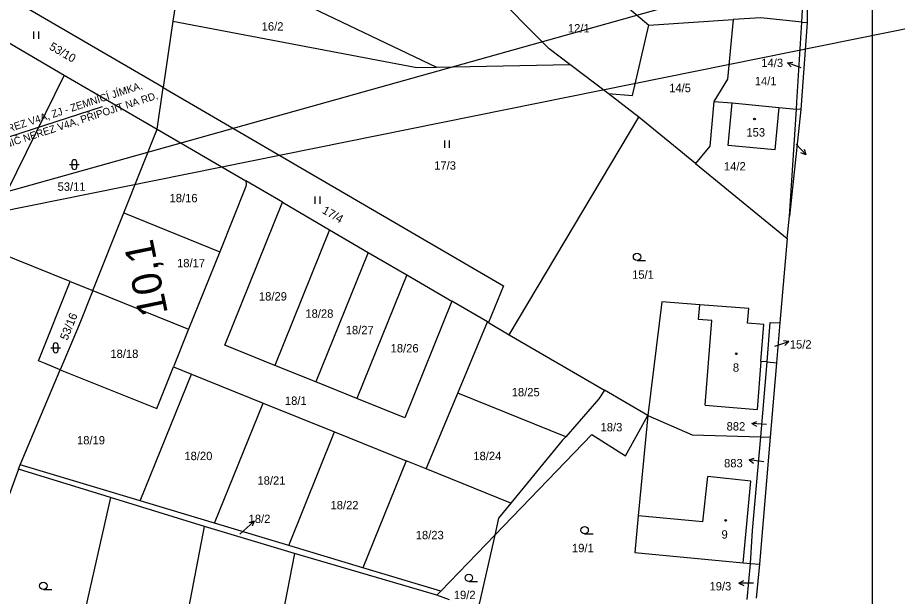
# Model space of a CAD drawing. Extents: x -553916 to -552953, y -1067470 to -1066637.
# Drawn here: x -553473.7 to -553294.9, y -1067063.1 to -1066945.3 of the extents above; entities that cross this region are included whole.
import ezdxf

# ---------------------------------------------------------------- set-up
doc = ezdxf.new("R2010")
doc.units = 0
for name, color, linetype in [('Hranice parcel', 7, 'Continuous'), ('Návěst místo trati', 7, 'Continuous'), ('Parcelní čísla', 7, 'Continuous'), ('Pop  PČ popisy', 7, 'Continuous'), ('trasa_NN_popisky', 7, 'Continuous'), ('Vnitřní kresba', 7, 'Continuous'), ('Vrstva 1', 7, 'Continuous'), ('Vrstva 28', 7, 'Continuous'), ('Značky budov', 7, 'Continuous'), ('Značky kultur', 7, 'Continuous')]:
    doc.layers.add(name, color=color, linetype=linetype)

msp = doc.modelspace()

# ---------------------------------------------------------------- linework, layer by layer
at = {"layer": 'Hranice parcel'}
for p, q in [((-553439.39, -1066931.05), (-553388.55, -1066955.44)), ((-553440.62, -1066935.71), (-553442.13, -1066946.08)), ((-553440.62, -1066935.71), (-553442.13, -1066946.08)), ((-553313.3, -1066937.87), (-553313.24, -1066946.37)), ((-553349.32, -1066943.54), (-553345.38, -1066946.85)), ((-553442.13, -1066946.08), (-553444.09, -1066959.55)), ((-553442.13, -1066946.08), (-553444.09, -1066959.55)), ((-553345.38, -1066946.85), (-553328.25, -1066945.75)), ((-553328.25, -1066945.75), (-553329.39, -1066957.87)), ((-553313.24, -1066946.37), (-553314.48, -1066964.04)), ((-553314.33, -1066946.26), (-553313.24, -1066946.37)), ((-553388.55, -1066955.44), (-553361.44, -1066954.89)), ((-553353.69, -1066960.78), (-553361.44, -1066954.89)), ((-553464.25, -1066957.05), (-553481.25, -1066991.64)), ((-553464.25, -1066957.05), (-553445.33, -1066968.05)), ((-553329.39, -1066957.87), (-553332.16, -1066962.42)), ((-553445.33, -1066968.05), (-553444.09, -1066959.55)), ((-553445.33, -1066968.05), (-553444.09, -1066959.55)), ((-553347.4, -1066965.57), (-553353.69, -1066960.78)), ((-553332.16, -1066962.42), (-553328.45, -1066962.7)), ((-553328.45, -1066962.7), (-553318.99, -1066963.61)), ((-553318.99, -1066963.61), (-553315.39, -1066963.95)), ((-553316.83, -1066985.76), (-553315.39, -1066963.95)), ((-553314.48, -1066964.04), (-553316.83, -1066985.76)), ((-553314.48, -1066964.04), (-553315.39, -1066963.95)), ((-553373.76, -1067009.84), (-553347.4, -1066965.57)), ((-553335.89, -1066975.02), (-553347.4, -1066965.57)), ((-553452.1, -1066985.07), (-553445.33, -1066968.05)), ((-553452.1, -1066985.07), (-553445.33, -1066968.05)), ((-553445.33, -1066968.05), (-553427.32, -1066978.56)), ((-553335.89, -1066975.02), (-553317.32, -1066990.26)), ((-553419.87, -1066982.91), (-553427.32, -1066978.56)), ((-553419.87, -1066982.91), (-553410.27, -1066988.51)), ((-553458.39, -1067000.88), (-553452.1, -1066985.07)), ((-553458.39, -1067000.88), (-553452.1, -1066985.07)), ((-553452.1, -1066985.07), (-553432.61, -1066992.95)), ((-553317.32, -1066990.26), (-553316.83, -1066985.76)), ((-553410.27, -1066988.51), (-553421.4, -1067016.07)), ((-553410.27, -1066988.51), (-553402.41, -1066993.09)), ((-553317.32, -1066990.26), (-553318.77, -1067007.4)), ((-553463.03, -1066999), (-553481.25, -1066991.64)), ((-553432.61, -1066992.95), (-553438.95, -1067008.73)), ((-553402.41, -1066993.09), (-553413.06, -1067019.44)), ((-553402.41, -1066993.09), (-553394.55, -1066997.68)), ((-553394.55, -1066997.68), (-553404.71, -1067022.81)), ((-553394.55, -1066997.68), (-553385.42, -1067003.02)), ((-553463.03, -1066999), (-553458.39, -1067000.88)), ((-553458.39, -1067000.88), (-553438.95, -1067008.73)), ((-553378.18, -1067007.25), (-553385.42, -1067003.02)), ((-553384.24, -1067021.73), (-553378.18, -1067007.25)), ((-553378.18, -1067007.25), (-553377.98, -1067007.37)), ((-553438.95, -1067008.73), (-553442.02, -1067016.38)), ((-553377.98, -1067007.37), (-553373.76, -1067009.84)), ((-553318.77, -1067007.4), (-553319.46, -1067015.54)), ((-553373.76, -1067009.84), (-553354.43, -1067021.12)), ((-553413.06, -1067019.44), (-553421.4, -1067016.07)), ((-553322.61, -1067030.64), (-553321.33, -1067015.39)), ((-553321.33, -1067015.39), (-553319.46, -1067015.54)), ((-553319.46, -1067015.54), (-553320.75, -1067030.7)), ((-553473.16, -1067036.3), (-553465, -1067016.95)), ((-553473.16, -1067036.3), (-553465, -1067016.95)), ((-553448.77, -1067043.63), (-553438.35, -1067017.86)), ((-553442.02, -1067016.38), (-553438.35, -1067017.86)), ((-553438.35, -1067017.86), (-553423.8, -1067023.74)), ((-553404.71, -1067022.81), (-553413.06, -1067019.44)), ((-553345.6, -1067026.28), (-553354.43, -1067021.12)), ((-553390.68, -1067037.12), (-553384.24, -1067021.73)), ((-553362.3, -1067030.59), (-553384.24, -1067021.73)), ((-553433.67, -1067048.17), (-553423.8, -1067023.74)), ((-553423.8, -1067023.74), (-553409.26, -1067029.62)), ((-553418.58, -1067052.7), (-553409.26, -1067029.62)), ((-553409.26, -1067029.62), (-553394.72, -1067035.49)), ((-553320.75, -1067030.7), (-553322.94, -1067056.53)), ((-553322.61, -1067030.64), (-553320.75, -1067030.7)), ((-553394.72, -1067035.49), (-553403.5, -1067057.23)), ((-553390.68, -1067037.12), (-553394.72, -1067035.49)), ((-553473.53, -1067037.17), (-553478.45, -1067050.68)), ((-553473.53, -1067037.17), (-553478.45, -1067050.68)), ((-553473.53, -1067037.17), (-553473.16, -1067036.3)), ((-553473.53, -1067037.17), (-553473.16, -1067036.3)), ((-553454.79, -1067042.97), (-553473.53, -1067037.17)), ((-553448.77, -1067043.63), (-553473.16, -1067036.3)), ((-553373.43, -1067044.09), (-553390.68, -1067037.12)), ((-553454.79, -1067042.97), (-553464.58, -1067086.32)), ((-553435.72, -1067048.88), (-553454.79, -1067042.97)), ((-553433.67, -1067048.17), (-553448.77, -1067043.63)), ((-553373.43, -1067044.09), (-553375.94, -1067047.15)), ((-553418.58, -1067052.7), (-553433.67, -1067048.17)), ((-553375.94, -1067047.15), (-553376.72, -1067050.6)), ((-553440.26, -1067072.6), (-553435.72, -1067048.88)), ((-553417.43, -1067054.37), (-553435.72, -1067048.88)), ((-553376.72, -1067050.6), (-553387.69, -1067061.98)), ((-553403.5, -1067057.23), (-553418.58, -1067052.7)), ((-553417.43, -1067054.37), (-553421.87, -1067077.19)), ((-553388.47, -1067062.79), (-553417.43, -1067054.37)), ((-553387.69, -1067061.98), (-553403.5, -1067057.23)), ((-553325.39, -1067063.72), (-553324.77, -1067056.36)), ((-553324.77, -1067056.36), (-553322.94, -1067056.53)), ((-553322.94, -1067056.53), (-553323.57, -1067063.41)), ((-553388.47, -1067062.79), (-553387.69, -1067061.98)), ((-553385.89, -1067063.74), (-553388.47, -1067062.79))]:
    msp.add_line(p, q, dxfattribs=at)
for points in [[(-553444.09, -1066959.55), (-553475.65, -1066941.14), (-553477.33, -1066939.99), (-553479.42, -1066936.25)], [(-553361.44, -1066954.89), (-553365.68, -1066951.68), (-553378.13, -1066939.08)], [(-553314.33, -1066946.26), (-553313.87, -1066938.65), (-553316.81, -1066938.4)], [(-553442.13, -1066946.08), (-553392.54, -1066955.52), (-553388.55, -1066955.44)], [(-553314.33, -1066946.26), (-553322.66, -1066945.39), (-553328.25, -1066945.75)], [(-553315.39, -1066963.95), (-553315.3, -1066962.52), (-553314.33, -1066946.26)], [(-553485.37, -1066948.09), (-553484.44, -1066947.42), (-553483.24, -1066947.01), (-553481.79, -1066947.03), (-553480.57, -1066947.51), (-553464.25, -1066957.05)], [(-553353.69, -1066960.78), (-553348.73, -1066961.16), (-553345.38, -1066946.85)], [(-553444.09, -1066959.55), (-553374.95, -1066999.88), (-553377.98, -1067007.37)], [(-553332.16, -1066962.42), (-553333.01, -1066971.51), (-553335.89, -1066975.02)], [(-553318.99, -1066963.61), (-553319.8, -1066972.22), (-553329.26, -1066971.34), (-553328.45, -1066962.7)], [(-553427.32, -1066978.56), (-553427.25, -1066979.21), (-553427.3, -1066979.71), (-553432.61, -1066992.95)], [(-553421.4, -1067016.07), (-553431.6, -1067011.96), (-553419.87, -1066982.91)], [(-553465, -1067016.95), (-553468.11, -1067015.69), (-553469.46, -1067015.14), (-553463.03, -1066999)], [(-553458.39, -1067000.88), (-553461.15, -1067007.82), (-553465, -1067016.95)], [(-553458.39, -1067000.88), (-553461.15, -1067007.82), (-553465, -1067016.95)], [(-553385.42, -1067003.02), (-553395, -1067026.73), (-553404.71, -1067022.81)], [(-553321.33, -1067015.39), (-553322.63, -1067015.29), (-553322.04, -1067007.78), (-553325.33, -1067007.52), (-553325.09, -1067004.53), (-553335.06, -1067003.74), (-553342.74, -1067003.13), (-553345.6, -1067026.28)], [(-553321.33, -1067015.39), (-553320.76, -1067007.38), (-553318.77, -1067007.4)], [(-553465, -1067016.95), (-553445.42, -1067024.86), (-553442.02, -1067016.38)], [(-553354.43, -1067021.12), (-553355.59, -1067022.89), (-553362.3, -1067030.59)], [(-553376.72, -1067050.6), (-553357.01, -1067030.14), (-553350.14, -1067034.5), (-553345.6, -1067026.28)], [(-553345.6, -1067026.28), (-553347.55, -1067046.67), (-553348.27, -1067054.17), (-553326.24, -1067056.22), (-553324.77, -1067056.36)], [(-553345.6, -1067026.28), (-553336.61, -1067030.21), (-553322.61, -1067030.64)], [(-553362.3, -1067030.59), (-553363, -1067031.39), (-553363.63, -1067032.12), (-553373.43, -1067044.09)], [(-553324.77, -1067056.36), (-553324.34, -1067049.67), (-553322.61, -1067030.64)], [(-553376.72, -1067050.6), (-553379.84, -1067064.34), (-553380.27, -1067066)]]:
    msp.add_lwpolyline(points, dxfattribs=at)
at = {"layer": 'Pop  PČ popisy'}
for p, q in [((-553317.24, -1066954.55), (-553316.13, -1066954.43)), ((-553314.42, -1066955.58), (-553317.24, -1066954.55)), ((-553317.24, -1066954.55), (-553316.47, -1066955.37)), ((-553315.48, -1066971.08), (-553313.43, -1066973.27)), ((-553313.43, -1066973.27), (-553314.48, -1066972.88)), ((-553313.43, -1066973.27), (-553313.75, -1066972.2)), ((-553319.81, -1067012.17), (-553316.96, -1067011.24)), ((-553316.96, -1067011.24), (-553318.06, -1067011.08)), ((-553316.96, -1067011.24), (-553317.75, -1067012.03)), ((-553324.49, -1067027.87), (-553323.45, -1067027.46)), ((-553321.5, -1067028.13), (-553324.49, -1067027.87)), ((-553324.49, -1067027.87), (-553323.54, -1067028.46)), ((-553325.03, -1067035.32), (-553323.97, -1067034.95)), ((-553322.05, -1067035.69), (-553325.03, -1067035.32)), ((-553325.03, -1067035.32), (-553324.1, -1067035.94)), ((-553427.85, -1067049.78), (-553425.62, -1067047.77)), ((-553425.62, -1067047.77), (-553426.7, -1067048.07)), ((-553425.62, -1067047.77), (-553426.03, -1067048.81)), ((-553428.54, -1067050.39), (-553427.85, -1067049.78)), ((-553327.1, -1067060.35), (-553326.1, -1067059.85)), ((-553324.1, -1067060.35), (-553327.1, -1067060.35)), ((-553327.1, -1067060.35), (-553326.1, -1067060.85))]:
    msp.add_line(p, q, dxfattribs=at)
at = {"layer": 'trasa_NN_popisky'}
msp.add_lwpolyline([(-553456.48, -1066963.51), (-553494.62, -1066975.85), (-553504.37, -1066990.3)], dxfattribs=at)
at = {"layer": 'Vnitřní kresba'}
for p, q in [((-553335.3, -1067006.73), (-553335.06, -1067003.74)), ((-553332.61, -1067006.94), (-553335.3, -1067006.73)), ((-553333.97, -1067024.16), (-553332.61, -1067006.94)), ((-553322.63, -1067015.29), (-553323.41, -1067025.02)), ((-553333.97, -1067024.16), (-553323.41, -1067025.02)), ((-553334.41, -1067047.93), (-553333.38, -1067038.66)), ((-553324.66, -1067039.63), (-553333.38, -1067038.66)), ((-553326.24, -1067056.22), (-553324.66, -1067039.63)), ((-553334.41, -1067047.93), (-553347.55, -1067046.67))]:
    msp.add_line(p, q, dxfattribs=at)
at = {"layer": 'Vrstva 1'}
msp.add_lwpolyline([(-553300, -1066816.27), (-553300, -1067100), (-553800, -1067100), (-553800, -1066816.27)], dxfattribs=at)
at = {"layer": 'Vrstva 28'}
for p, q in [((-553261.02, -1066920.51), (-553514.46, -1066991.61)), ((-553504.37, -1066990.3), (-553260.21, -1066940.91))]:
    msp.add_line(p, q, dxfattribs=at)
at = {"layer": 'Značky budov'}
for centre in [(-553323.92, -1066965.97), (-553327.63, -1067013.71), (-553329.78, -1067047.61)]:
    msp.add_circle(centre, 0.175, dxfattribs=at)
at = {"layer": 'Značky kultur'}
for p, q in [((-553470.38, -1066949.65), (-553470.38, -1066948.15)), ((-553469.38, -1066949.65), (-553469.38, -1066948.15)), ((-553386.89, -1066971.82), (-553386.89, -1066970.32)), ((-553385.89, -1066971.82), (-553385.89, -1066970.32)), ((-553462.65, -1066974.74), (-553462.65, -1066975.74)), ((-553461.65, -1066975.74), (-553461.65, -1066974.74)), ((-553463.15, -1066975.24), (-553461.15, -1066975.24)), ((-553413.2, -1066983.2), (-553413.2, -1066981.7)), ((-553412.2, -1066983.2), (-553412.2, -1066981.7)), ((-553347.8, -1066994.76), (-553346.05, -1066994.76)), ((-553466.96, -1067012.5), (-553464.96, -1067012.5)), ((-553466.46, -1067012), (-553466.46, -1067013)), ((-553465.46, -1067013), (-553465.46, -1067012)), ((-553358.45, -1067050.36), (-553356.7, -1067050.36)), ((-553381.99, -1067060.04), (-553380.24, -1067060.04)), ((-553468.45, -1067061.67), (-553466.7, -1067061.67))]:
    msp.add_line(p, q, dxfattribs=at)
for centre in [(-553347.8, -1066994.01), (-553358.45, -1067049.61), (-553381.99, -1067059.29), (-553468.45, -1067060.92)]:
    msp.add_circle(centre, 0.75, dxfattribs=at)
for centre, start, end in [((-553462.15, -1066974.74), 0, 180), ((-553462.15, -1066975.74), 180, 359.9879), ((-553465.96, -1067012), 0, 180), ((-553465.96, -1067013), 180, 359.9879)]:
    msp.add_arc(centre, 0.5, start, end, dxfattribs=at)

# ---------------------------------------------------------------- texts
at = {"layer": 'Návěst místo trati'}
msp.add_text('10,1', height=6, rotation=101.7156, dxfattribs=at).set_placement((-553443.11, -1067005.44))
at = {"layer": 'Parcelní čísla'}
for s, p in [('16/2', (-553424.08, -1066947.98)), ('12/1', (-553361.85, -1066948.36)), ('14/3', (-553322.54, -1066955.4)), ('14/5', (-553341.27, -1066960.51)), ('14/1', (-553323.87, -1066959.1)), ('153', (-553325.57, -1066969.53)), ('17/3', (-553389.02, -1066976.27)), ('14/2', (-553330.13, -1066976.44)), ('53/11', (-553465.56, -1066980.57)), ('18/16', (-553442.8, -1066982.9)), ('18/17', (-553441.28, -1066996.12)), ('15/1', (-553348.8, -1066998.46)), ('18/29', (-553424.64, -1067002.89)), ('18/28', (-553415.2, -1067006.39)), ('18/27', (-553407, -1067009.74)), ('18/26', (-553397.88, -1067013.44)), ('15/2', (-553316.75, -1067012.66)), ('18/18', (-553454.83, -1067014.57)), ('8', (-553328.32, -1067017.37)), ('18/25', (-553373.27, -1067022.37)), ('18/1', (-553419.36, -1067024.11)), ('18/3', (-553355.21, -1067029.5)), ('882', (-553329.6, -1067029.33)), ('18/19', (-553461.61, -1067032.15)), ('18/20', (-553439.79, -1067035.35)), ('18/24', (-553381.07, -1067035.35)), ('883', (-553330.11, -1067036.82)), ('18/21', (-553424.94, -1067040.35)), ('18/22', (-553410.09, -1067045.36)), ('18/2', (-553426.74, -1067048.14)), ('18/23', (-553392.77, -1067051.44)), ('9', (-553330.63, -1067051.31)), ('19/1', (-553361.02, -1067054.07)), ('19/3', (-553333.07, -1067061.85)), ('19/2', (-553385.04, -1067063.61))]:
    msp.add_text(s, height=1.7, dxfattribs=at).set_placement(p)
for s, rotation, p in [('53/10', 330, (-553467.41, -1066951.71)), ('17/4', 330, (-553411.95, -1066985.01)), ('53/16', 68, (-553463.58, -1067011.11))]:
    msp.add_text(s, height=1.7, rotation=rotation, dxfattribs=at).set_placement(p)
at = {"layer": 'trasa_NN_popisky'}
for s, p in [('ZEMNÍCÍ PÁSEK NEREZ V4A, ZJ - ZEMNÍCÍ JÍMKA, ', (-553493.42, -1066974.51)), ('HLOUBKOVÝ ZEMNIČ NEREZ V4A, PŘIPOJIT NA RD,', (-553492.52, -1066977.25))]:
    msp.add_text(s, height=1.5, rotation=18.0426, dxfattribs=at).set_placement(p)

doc.saveas('drawing.dxf')
